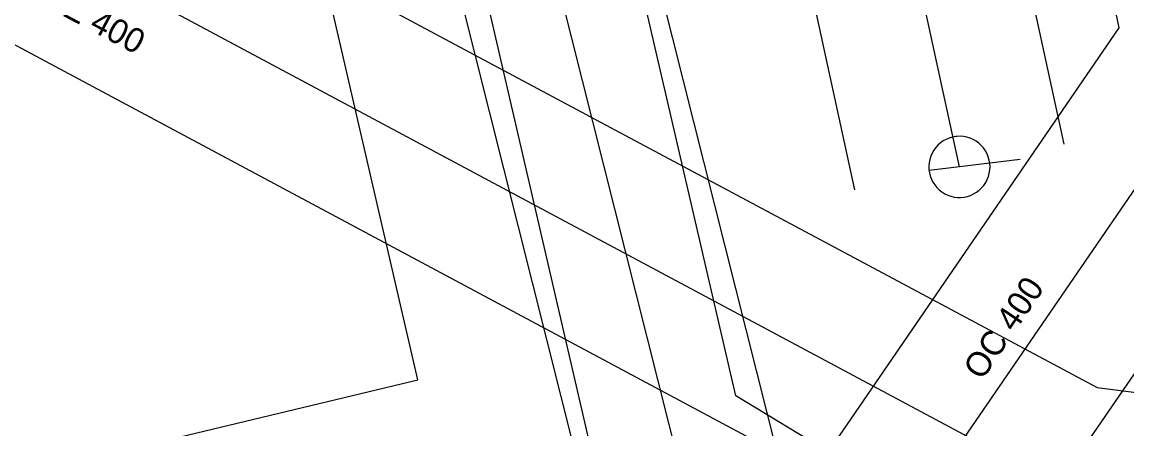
# Model space of a CAD drawing. Extents: x -762993 to -761845, y -975230 to -974501.
# Drawn here: x -762287.32 to -762269.27, y -975003.77 to -974997.12 of the extents above; entities that cross this region are included whole.
import ezdxf

# ---------------------------------------------------------------- set-up
doc = ezdxf.new("R2010")
doc.units = 0
for name, color, linetype in [('IS_CEZ-T_parovod', 7, 'Continuous'), ('IS_CEZ-T_parovod OP', 7, 'Continuous'), ('IS_SCVK_kanalizace anotace', 7, 'Continuous'), ('IS_SCVK_kanalizace jednotna', 7, 'Continuous'), ('IS_SCVK_kanalizace OP', 7, 'Continuous'), ('IS_SCVK_kanalizace znaky', 7, 'Continuous'), ('IS_SCVK_vodovod anotace', 7, 'Continuous'), ('IS_SCVK_vodovod OP', 7, 'Continuous'), ('IS_SCVK_vodovod privadec', 7, 'Continuous')]:
    doc.layers.add(name, color=color, linetype=linetype)

msp = doc.modelspace()

# ---------------------------------------------------------------- linework, layer by layer
at = {"layer": 'IS_CEZ-T_parovod'}
msp.add_line((-762277.86, -975004.82), (-762282.64, -974984.16), dxfattribs=at)
at = {"layer": 'IS_CEZ-T_parovod OP'}
for p, q in [((-762280.855, -975002.967), (-762285.076, -974984.724)), ((-762275.663, -975003.227), (-762279.634, -974986.061))]:
    msp.add_line(p, q, dxfattribs=at)
for points in [[(-762303.135, -975025.276), (-762298.052, -975007.092), (-762280.855, -975002.967)], [(-761996.08, -975126.67), (-762038.774, -975079.115), (-762091.626, -975020.854), (-762093.44, -975020.521), (-762094.885, -975020.389), (-762136.848, -975016.968), (-762136.601, -975013.108), (-762144.22, -975012.36), (-762144.673, -975016.562), (-762187.153, -975012.956), (-762186.891, -975008.753), (-762196.252, -975008.084), (-762196.617, -975011.538), (-762236.693, -975007.904), (-762236.55, -975004.089), (-762245.225, -975003.61), (-762245.498, -975006.816), (-762252.395, -975006.198), (-762273.338, -975004.632), (-762275.663, -975003.227)]]:
    msp.add_lwpolyline(points, dxfattribs=at)
at = {"layer": 'IS_SCVK_kanalizace jednotna'}
for points in [[(-762272.009, -974999.487), (-762282.203, -974952.631)], [(-762299.318, -974989.209), (-762270.284, -975004.741)]]:
    msp.add_lwpolyline(points, dxfattribs=at)
at = {"layer": 'IS_SCVK_kanalizace OP'}
for p, q in [((-762298.611, -974987.659), (-762269.759, -975003.094)), ((-762300.025, -974990.759), (-762270.809, -975006.388)), ((-762269.759, -975003.094), (-762233.103, -975007.725))]:
    msp.add_line(p, q, dxfattribs=at)
for points in [[(-762270.299, -974999.115), (-762280.493, -974952.259)], [(-762273.719, -974999.859), (-762283.913, -974953.003)]]:
    msp.add_lwpolyline(points, dxfattribs=at)
at = {"layer": 'IS_SCVK_kanalizace znaky'}
for points in [[(-762272.068, -974998.991), (-762272.122, -974999), (-762272.175, -974999.015), (-762272.226, -974999.037), (-762272.273, -974999.062), (-762272.318, -974999.094), (-762272.359, -974999.13), (-762272.396, -974999.171), (-762272.428, -974999.215), (-762272.456, -974999.263), (-762272.477, -974999.312), (-762272.493, -974999.365), (-762272.503, -974999.419), (-762272.508, -974999.474), (-762272.507, -974999.528), (-762272.499, -974999.583), (-762272.486, -974999.635), (-762272.467, -974999.687), (-762272.443, -974999.736), (-762272.412, -974999.782), (-762272.378, -974999.824), (-762272.339, -974999.863), (-762272.296, -974999.896), (-762272.249, -974999.925), (-762272.199, -974999.949), (-762272.148, -974999.967), (-762272.095, -974999.979), (-762272.04, -974999.986), (-762271.986, -974999.986), (-762271.931, -974999.981), (-762271.878, -974999.969), (-762271.826, -974999.952), (-762271.776, -974999.929), (-762271.729, -974999.902), (-762271.685, -974999.869), (-762271.645, -974999.831), (-762271.61, -974999.789), (-762271.579, -974999.744), (-762271.554, -974999.695), (-762271.534, -974999.644), (-762271.52, -974999.591), (-762271.511, -974999.537), (-762271.508, -974999.483), (-762271.512, -974999.427), (-762271.522, -974999.374), (-762271.537, -974999.321), (-762271.557, -974999.271), (-762271.584, -974999.223), (-762271.616, -974999.177), (-762271.652, -974999.137), (-762271.692, -974999.1), (-762271.736, -974999.067), (-762271.784, -974999.04), (-762271.834, -974999.018), (-762271.886, -974999.002), (-762271.939, -974998.992), (-762271.995, -974998.987), (-762272.05, -974998.989), (-762272.068, -974998.991)], [(-762271.015, -974999.368), (-762272.505, -974999.547)]]:
    msp.add_lwpolyline(points, dxfattribs=at)
at = {"layer": 'IS_SCVK_vodovod OP'}
for p, q in [((-762279.692, -974985.479), (-762274.766, -975005.04)), ((-762271.863, -974985.652), (-762269.402, -974997.215)), ((-762282.49, -974987.47), (-762277.378, -975007.772)), ((-762269.402, -974997.215), (-762274.766, -975005.04)), ((-762265.932, -974998.166), (-762273.888, -975009.773))]:
    msp.add_line(p, q, dxfattribs=at)
at = {"layer": 'IS_SCVK_vodovod privadec'}
for points in [[(-762281.341, -974985.482), (-762275.528, -975008.565)], [(-762267.587, -974997.574), (-762275.202, -975008.684)]]:
    msp.add_lwpolyline(points, dxfattribs=at)

# ---------------------------------------------------------------- texts
at = {"layer": 'IS_SCVK_kanalizace anotace'}
msp.add_text('BE 400', height=0.4, rotation=332, dxfattribs=at).set_placement((-762287.004, -974996.833))
at = {"layer": 'IS_SCVK_vodovod anotace'}
msp.add_text('OC 400', height=0.4, rotation=56, dxfattribs=at).set_placement((-762271.638, -975002.99))

doc.saveas('drawing.dxf')
